// Mitsubishi GX Works2 project: 变址应用练习   PLC: FX3U/FX3UC

PROGRAM MAIN
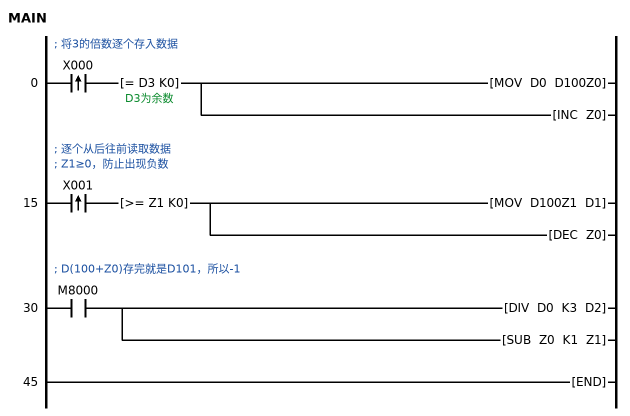
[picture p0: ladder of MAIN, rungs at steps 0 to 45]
; 将3的倍数逐个存入数据
0     LDP     X000
      AND=    D3 K0  ; D3为余数
      MOV     D0 D100Z0
        [note] 把D0的数据传到D(100+Z0）
      INC     Z0
        [note] Z0自加一
; 逐个从后往前读取数据
; Z1≥0，防止出现负数
15    LDP     X001
      AND>=   Z1 K0
      MOV     D100Z1 D1
        [note] 把D(100+Z1)的数据传到D1
      DEC     Z0
        [note] Z0自减一
; D(100+Z0)存完就是D101，所以-1
30    LD      M8000
      DIV     D0 K3 D2
        [note] D0除以3，商放在D2,余数放在D3
      SUB     Z0 K1 Z1
        [note] Z0-1传到Z1
45    END
END_PROGRAM
